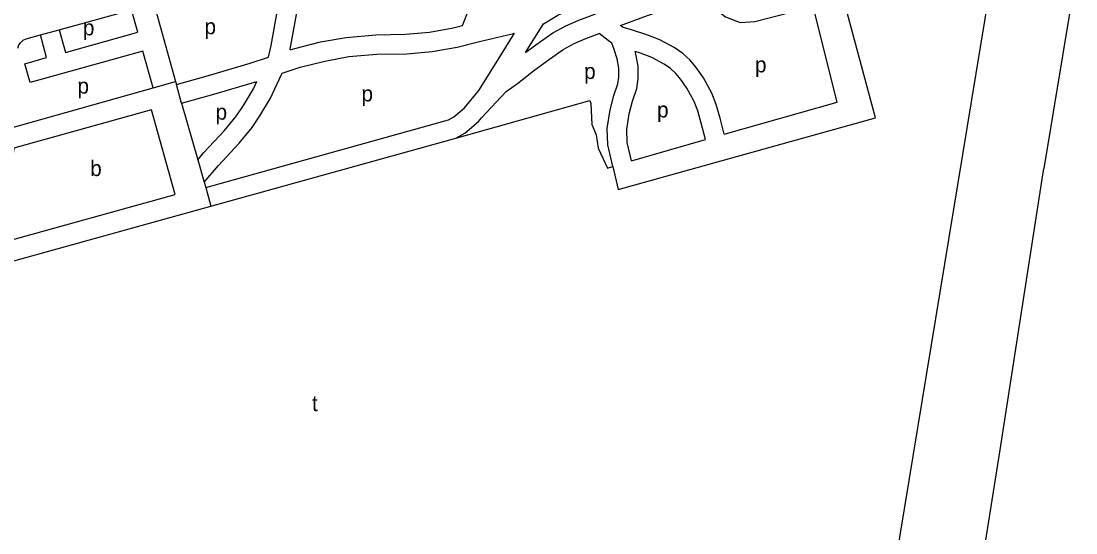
# Model space of a CAD drawing. Extents: x 158358 to 160383, y 379531 to 380764.
# Drawn here: x 160024.2 to 160295.5, y 380106.3 to 380237.9 of the extents above; entities that cross this region are included whole.
import ezdxf

# ---------------------------------------------------------------- set-up
doc = ezdxf.new("R2010")
doc.units = 0
for name, color, linetype in [('BLT_Basislijn', 7, 'Continuous'), ('BLT_Bebouwing', 7, 'Continuous'), ('BLT_Centroide', 7, 'Continuous')]:
    doc.layers.add(name, color=color, linetype=linetype)

msp = doc.modelspace()

# ---------------------------------------------------------------- linework, layer by layer
at = {"layer": 'BLT_Basislijn'}
for p, q in [((160295.54, 380250), (160287.26, 380199.97)), ((160033.96, 380235.66), (160052.56, 380240.82)), ((160054.18, 380235.02), (160052.56, 380240.82)), ((160058.34, 380242.42), (160063.94, 380222.35)), ((160029.14, 380234.33), (160033.96, 380235.66)), ((160058.15, 380220.73), (160055.52, 380230.2)), ((160058.15, 380220.73), (160063.94, 380222.35)), ((160063.94, 380222.35), (160064.14, 380221.62)), ((160065.49, 380216.8), (160064.14, 380221.62)), ((160065.49, 380216.8), (160069.64, 380202.26)), ((160069.64, 380202.26), (160071.3, 380196.45)), ((160276.04, 380127.72), (160287.26, 380199.97)), ((160071.3, 380196.45), (160071.67, 380195.15)), ((160071.67, 380195.15), (160073.01, 380190.33)), ((160267.15, 380072.02), (160276.04, 380127.72))]:
    msp.add_line(p, q, dxfattribs=at)
for points in [[(160158.56, 380237.21), (160162.29, 380239.44), (160168.62, 380242.34), (160173.37, 380244.84), (160178.72, 380247.85), (160184.14, 380253.06), (160187.26, 380257.17), (160190.19, 380260.77), (160194.13, 380265.37), (160197.91, 380269.43), (160201.34, 380272.53)], [(160137.7, 380236.73), (160139.4, 380240.86), (160142.62, 380247.7), (160146.78, 380257.96), (160149.11, 380265.24), (160149.75, 380267.74)], [(160273.02, 380260.23), (160275.56, 380259.4), (160247.94, 380091.73)], [(160087.85, 380228.59), (160088.53, 380231.65), (160092.15, 380251.78)], [(160093.39, 380230.48), (160093.43, 380230.67), (160097.49, 380253.26)], [(160153.94, 380229.81), (160156.56, 380231.76), (160160.99, 380234.89), (160164.33, 380236.67), (160167.63, 380238.1), (160175.67, 380241.12), (160182.7, 380243.7), (160192.47, 380247.11), (160198.59, 380249.14)], [(160176.4, 380200.53), (160177.79, 380194.61), (160243.96, 380213.05), (160234, 380250)], [(160178.34, 380236.78), (160184.38, 380238.99), (160194.08, 380242.38), (160200.4, 380244.47)], [(160200.4, 380244.47), (160200.61, 380244.05), (160202.66, 380241.13), (160205.36, 380239.03), (160209.19, 380237.5), (160212.93, 380237.77), (160227.93, 380241.64)], [(160205.08, 380208.8), (160234.08, 380217.08), (160227.93, 380241.64)], [(160033.96, 380235.66), (160035.58, 380229.84), (160054.18, 380235.02)], [(160093.39, 380230.48), (160094.57, 380230.89), (160101.25, 380232.52), (160107.83, 380233.71), (160115.43, 380234.35), (160123.11, 380234.5), (160129.26, 380235.05), (160135.31, 380236.13), (160137.7, 380236.73)], [(160153.94, 380229.81), (160158.56, 380237.21)], [(160205.08, 380208.8), (160203.99, 380212.94), (160203, 380216.44), (160201.84, 380219.36), (160199.71, 380223.31), (160197.88, 380225.95), (160196.27, 380227.81), (160194.43, 380229.59), (160192.21, 380231.12), (160188.49, 380233.07), (160185.16, 380234.32), (160181.22, 380235.62), (160179.1, 380236.23), (160178.34, 380236.78)], [(160023.36, 380230.91), (160023.63, 380231.76), (160024.09, 380232.43), (160024.73, 380232.98), (160025.52, 380233.33), (160029.14, 380234.33)], [(160055.52, 380230.2), (160026.51, 380222.12), (160025.17, 380226.94), (160030.76, 380228.5), (160029.14, 380234.33)], [(160091.37, 380224.48), (160095.99, 380226.09), (160102.29, 380227.63), (160108.49, 380228.75), (160115.69, 380229.36), (160123.39, 380229.5), (160129.92, 380230.09), (160136.37, 380231.23), (160142.1, 380232.69), (160150.89, 380234.71), (160151.14, 380234.77)], [(160134.13, 380212.51), (160135.51, 380213.25), (160138.27, 380215.59), (160141.96, 380220.08), (160145.96, 380226.47), (160151.14, 380234.77)], [(160142.68, 380213.08), (160148.97, 380219.76), (160151.88, 380221.89), (160156.01, 380225.12), (160159.5, 380227.71), (160163.62, 380230.63), (160166.5, 380232.16), (160169.5, 380233.46), (160172.87, 380234.73)], [(160176.12, 380232.22), (160175.19, 380232.88), (160172.87, 380234.73)], [(160176.4, 380200.53), (160175.1, 380206.05), (160174.99, 380210.31), (160175.7, 380215.1), (160176.67, 380218.74), (160177.68, 380221.78), (160177.95, 380223.46), (160177.93, 380225.82), (160177.5, 380228.19), (160176.77, 380230.62), (160176.12, 380232.22)], [(160181.19, 380201.99), (160180.08, 380206.69), (160180, 380210), (160180.6, 380214.09), (160181.46, 380217.31), (160182.56, 380220.59), (160182.95, 380223.08), (160182.93, 380226.29), (160182.36, 380229.36), (160182.16, 380230.05)], [(160200.27, 380207.43), (160199.16, 380211.62), (160198.26, 380214.84), (160197.3, 380217.24), (160195.44, 380220.69), (160193.92, 380222.88), (160192.63, 380224.38), (160191.26, 380225.71), (160189.62, 380226.83), (160186.44, 380228.5), (160183.49, 380229.61), (160182.16, 380230.05)], [(160064.14, 380221.62), (160072.36, 380223.95), (160083.13, 380227.08), (160087.85, 380228.59)], [(160071.3, 380196.45), (160074.95, 380200.81), (160080.27, 380206.51), (160083.62, 380210.54), (160085.62, 380213.52), (160088.38, 380218.1), (160091.1, 380224.03), (160091.37, 380224.48)], [(160065.49, 380216.8), (160073.74, 380219.14), (160084.84, 380222.37)], [(160069.64, 380202.26), (160071.21, 380204.13), (160076.52, 380209.81), (160079.61, 380213.54), (160081.4, 380216.2), (160083.95, 380220.44), (160084.84, 380222.37)], [(160020.43, 380210.12), (160058.15, 380220.73)], [(160135.99, 380207.84), (160170.53, 380217.44)], [(160170.53, 380217.44), (160170.74, 380216.73), (160171, 380211.33), (160172.13, 380208.66), (160172.66, 380205.19), (160175.06, 380200.05), (160176.4, 380200.53)], [(160071.67, 380195.15), (160134.13, 380212.51)], [(160135.99, 380207.84), (160138.34, 380209.09), (160141.84, 380212.07), (160142.68, 380213.08)], [(160073.01, 380190.33), (160135.99, 380207.84)], [(160181.19, 380201.99), (160200.27, 380207.43)], [(160019.2, 380175.38), (160073.01, 380190.33)]]:
    msp.add_lwpolyline(points, dxfattribs=at)
at = {"layer": 'BLT_Bebouwing'}
msp.add_lwpolyline([(160022.32, 380205.25), (160019.31, 380181.02), (160063.8, 380193.36), (160057.76, 380215.1), (160022.32, 380205.25)], dxfattribs=at)

# ---------------------------------------------------------------- texts
at = {"layer": 'BLT_Centroide'}
for s, p in [('p', (160040.08, 380234.23)), ('p', (160071.36, 380234.51)), ('p', (160212.97, 380224.72)), ('p', (160169.02, 380223.01)), ('p', (160038.68, 380219.24)), ('p', (160111.74, 380217.25)), ('p', (160187.78, 380213.12)), ('p', (160074.21, 380212.55)), ('b', (160041.96, 380198.06)), ('t', (160099.03, 380137.64))]:
    msp.add_text(s, height=4, dxfattribs=at).set_placement(p)

doc.saveas('drawing.dxf')
